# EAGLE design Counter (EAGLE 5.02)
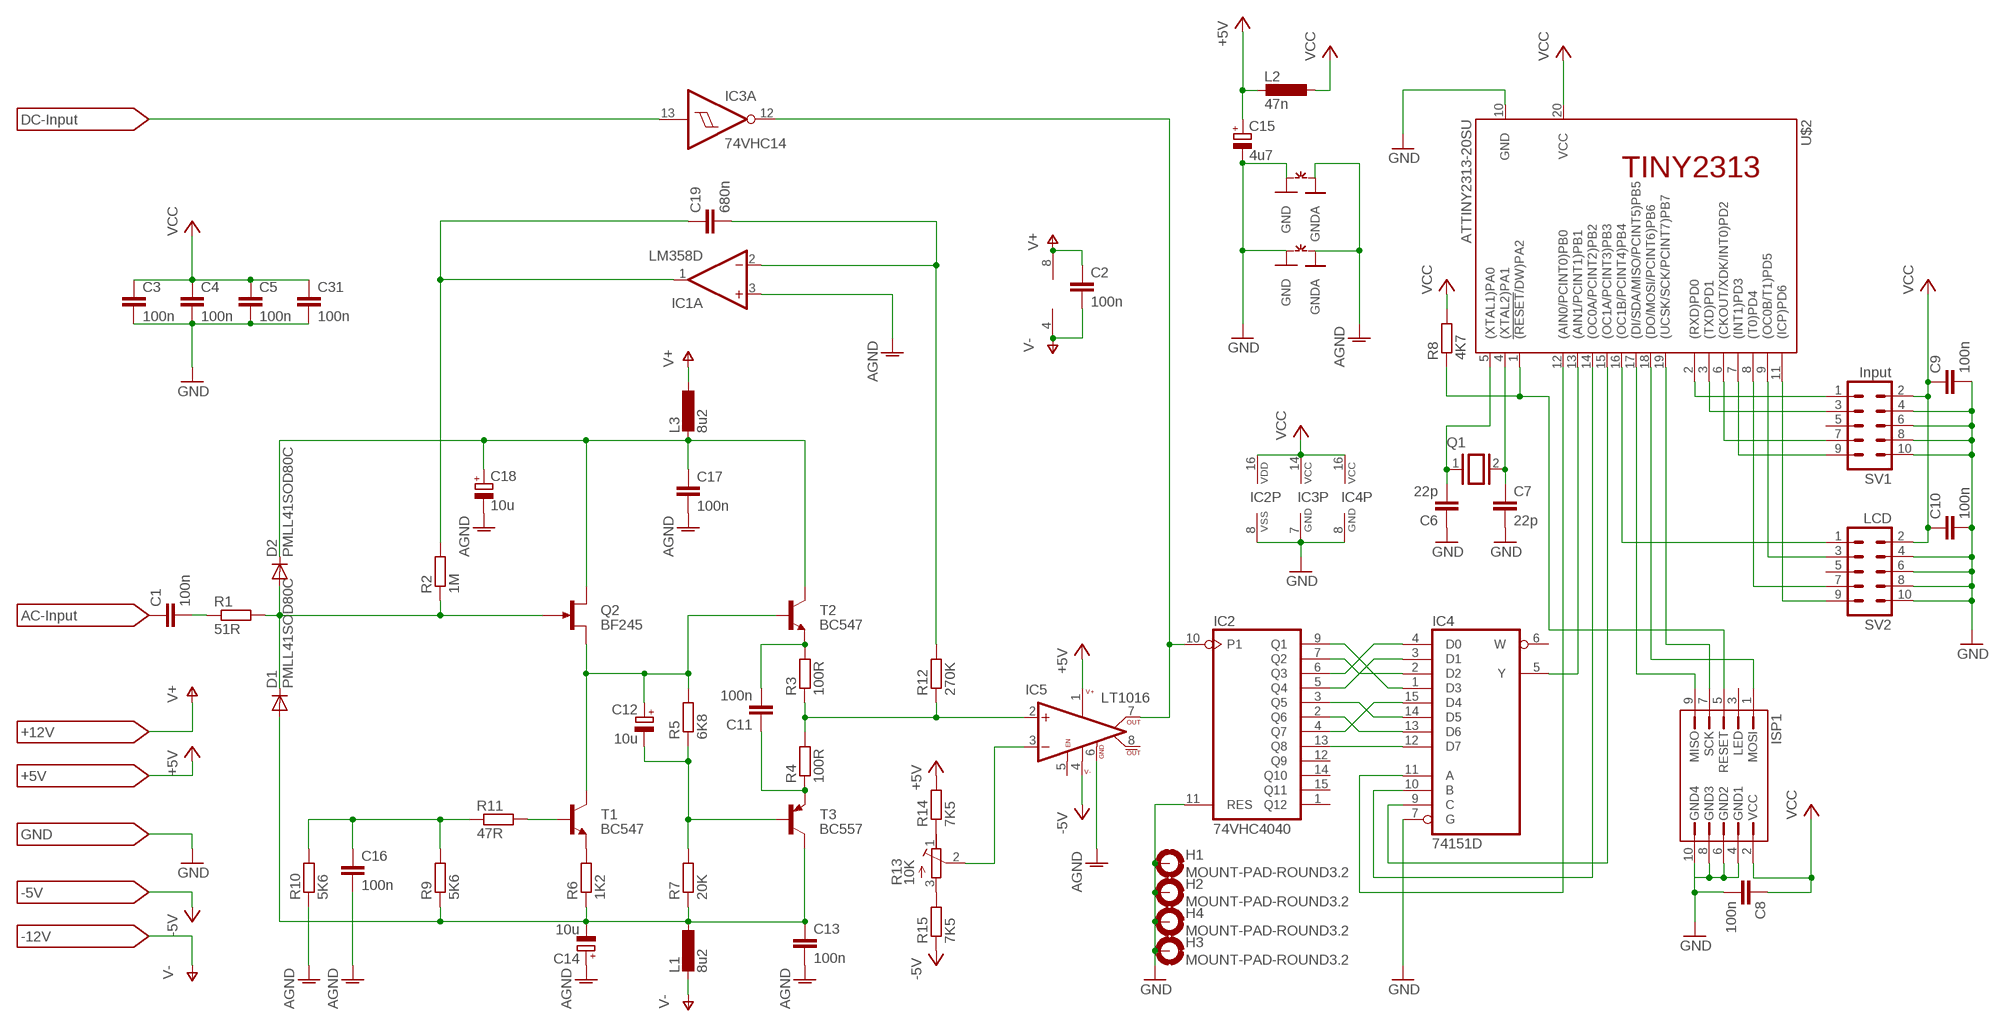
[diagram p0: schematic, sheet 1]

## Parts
C1  100n  C-EUC0603  [C0603]
C2  100n  C-EUC0603  [C0603]
C3  100n  C-EUC0603  [C0603]
C4  100n  C-EUC0603  [C0603]
C5  100n  C-EUC0603  [C0603]
C6  22p  C-EUC0603  [C0603]
C7  22p  C-EUC0603  [C0603]
C8  100n  C-EUC0603  [C0603]
C9  100n  C-EUC0603  [C0603]
C10  100n  C-EUC0603  [C0603]
C11  100n  C-EUC0603  [C0603]
C12  10u  CPOL-EUE2.5-5  [E2,5-5]
C13  100n  C-EUC0603  [C0603]
C14  10u  CPOL-EUE2.5-5  [E2,5-5]
C15  4u7  CPOL-EUE2.5-5  [E2,5-5]
C16  100n  C-EUC0603  [C0603]
C17  100n  C-EUC0603  [C0603]
C18  10u  CPOL-EUE2.5-5  [E2,5-5]
C19  680n  C-EUC0603  [C0603]
C31  100n  C-EUC0603  [C0603]
D1  PMLL41SOD80C  [SOD80C]
D2  PMLL41SOD80C  [SOD80C]
H1  MOUNT-PAD-ROUND3.2  [3,2-PAD]
H2  MOUNT-PAD-ROUND3.2  [3,2-PAD]
H3  MOUNT-PAD-ROUND3.2  [3,2-PAD]
H4  MOUNT-PAD-ROUND3.2  [3,2-PAD]
IC1  LM358D  [SO08]
IC2  74VHC4040  4040D  [SO16]
IC3  74VHC14  74HCT14D  [SO14]
IC4  74151D  [SO16]
IC5  LT1016  LT1016CS8  [SOIC8]
ISP1  AVR-ISP-10  [ML10]
L1  8u2  L-EU0207/10  [0207/10]
L2  47n  L-EU0207/10  [0207/10]
L3  8u2  L-EU0207/10  [0207/10]
Q1  XTAL/S  [QS]
Q2  BF245  [SOT54C]
R1  51R  R-EU_R0805  [R0805]
R2  1M  R-EU_R0805  [R0805]
R3  100R  R-EU_R0805  [R0805]
R4  100R  R-EU_R0805  [R0805]
R5  6K8  R-EU_R0805  [R0805]
R6  1K2  R-EU_R0805  [R0805]
R7  20K  R-EU_R0805  [R0805]
R8  4K7  R-EU_R0805  [R0805]
R9  5K6  R-EU_R0805  [R0805]
R10  5K6  R-EU_R0805  [R0805]
R11  47R  R-EU_R0805  [R0805]
R12  270K  R-EU_R0805  [R0805]
R13  10K  R-TRIMM43P  [RTRIM43P]
R14  7K5  R-EU_R0805  [R0805]
R15  7K5  R-EU_R0805  [R0805]
SV1  Input  ML10  [ML10]
SV2  LCD  ML10  [ML10]
T1  BC547  [TO92]
T2  BC547  [TO92]
T3  BC557  [TO92]
U$1  +12V  LABEL-R  [CON-1]
U$2  ATTINY2313-20SU  [SOIC20S]
U$3  AC-Input  LABEL-R  [CON-1]
U$4  +5V  LABEL-R  [CON-1]
U$5  GND  LABEL-R  [CON-1]
U$6  DC-Input  LABEL-R  [CON-1]
U$7  -5V  LABEL-R  [CON-1]
U$8  -12V  LABEL-R  [CON-1]
~NUDEV~1  GND-GNDA1,27MM  [GND-GNDA-1,27MM]
~NUDEV~2  GND-GNDA1,27MM  [GND-GNDA-1,27MM]

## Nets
+5V [power]: C15.+ IC5.1(V+) L2.2 R14.2 U$4.P$1
-5V: IC5.4(V-) R15.1 U$7.P$1
AGND: C13.2 C14.+ C16.2 C17.2 C18.- IC1.3(A:+IN) IC5.6(GND) R10.1 ~NUDEV~1.GNDA ~NUDEV~2.GNDA
CLOCK [special]: IC3.13(A:I) U$6.P$1
GND: C3.2 C4.2 C5.2 C6.1 C7.2 C8.2 C9.2 C10.2 C15.- C31.2 H1.B3,2(MOUNT) H2.B3,2(MOUNT) H3.B3,2(MOUNT) H4.B3,2(MOUNT) IC2.8(VSS) IC2.11(RES) IC3.7(P:GND) IC4.7(G) IC4.8(GND) ISP1.4(GND1) ISP1.6(GND2) ISP1.8(GND3) ISP1.10(GND4) SV1.4 SV1.6 SV1.8 SV1.10 SV2.4 SV2.6 SV2.8 SV2.10 U$2.10(GND) U$5.P$1 ~NUDEV~1.GND ~NUDEV~2.GND
N$1: C1.1 U$3.P$1
N$2: C1.2 R1.1
N$3: IC2.10(P1) IC3.12(A:O) IC5.7(OUT)
N$4: D1.C D2.A Q2.G R1.2 R2.1
N$5: IC4.5(Y) U$2.13((AIN1/PCINT1)PB1)
N$6: IC2.13(Q8) IC4.12(D7)
N$7: C16.1 R9.2 R10.2 R11.1
N$8: IC5.2(+IN) R3.1 R4.2 R12.1
N$9: IC4.11(A) U$2.12((AIN0/PCINT0)PB0)
N$10: IC2.2(Q6) IC4.13(D6)
N$11: IC2.3(Q5) IC4.14(D5)
N$12: IC2.4(Q7) IC4.15(D4)
N$13: IC2.5(Q4) IC4.3(D1)
N$14: IC2.6(Q3) IC4.4(D0)
N$15: IC2.7(Q2) IC4.2(D2)
N$16: IC2.9(Q1) IC4.1(D3)
N$17: C11.2 R3.2 T2.1(E)
N$18: C6.2 Q1.1 U$2.5((XTAL1)PA0)
N$19: C7.1 Q1.2 U$2.4((XTAL2)PA1)
N$20: ISP1.7(SCK) U$2.19((UCSK/SCK/PCINT7)PB7)
N$21: IC4.10(B) U$2.14((OC0A/PCINT2)PB2)
N$22: IC4.9(C) U$2.15((OC1A/PCINT3)PB3)
N$23: ISP1.1(MOSI) U$2.18((DO/MOSI/PCINT6)PB6)
N$24: ISP1.9(MISO) U$2.17((DI/SDA/MISO/PCINT5)PB5)
N$25: ISP1.5(RESET) R8.1 U$2.1(!(RESET!/DW)PA2)
N$26: C11.1 R4.1 T3.1(E)
N$27: R11.2 T1.2(B)
N$29: C12.+ Q2.S R5.2 T1.3(C) T2.2(B)
N$30: SV1.1 U$2.2((RXD)PD0)
N$31: SV1.3 U$2.3((TXD)PD1)
N$32: SV1.7 U$2.6((CKOUT/XDK/INT0)PD2)
N$33: SV1.9 U$2.7((INT1)PD3)
N$34: SV2.1 U$2.16((OC1B/PCINT4)PB4)
N$35: SV2.3 U$2.9((OC0B/T1)PD5)
N$36: SV2.7 U$2.8((T0)PD4)
N$37: SV2.9 U$2.11((ICP)PD6)
N$38: C12.- R5.1 R7.2 T3.2(B)
N$39: C17.1 C18.+ D2.C L3.2 Q2.D T2.3(C)
N$40: R6.2 T1.1(E)
N$41: C13.1 C14.- D1.A L1.1 R6.1 R7.1 R9.1 T3.3(C)
N$42: C19.2 IC1.2(A:-IN) R12.2
N$44: C19.1 IC1.1(A:OUT) R2.2
N$45: R13.1(A) R14.1
N$46: R13.3(E) R15.2
N$47: IC5.3(-IN) R13.2(S)
V+: C2.1 IC1.8(P:V+) L3.1 U$1.P$1
V-: C2.2 IC1.4(P:V-) L1.2 U$8.P$1
VCC: C3.1 C4.1 C5.1 C8.1 C9.1 C10.1 C31.1 IC2.16(VDD) IC3.14(P:VCC) IC4.16(VCC) ISP1.2(VCC) L2.1 R8.2 SV1.2 SV2.2 U$2.20(VCC)
Unconnected: IC1.5(B:+IN) IC1.6(B:-IN) IC1.7(B:OUT) IC2.1(Q12) IC2.12(Q9) IC2.14(Q10) IC2.15(Q11) IC3.1(D:I) IC3.2(D:O) IC3.3(E:I) IC3.4(E:O) IC3.5(F:I) IC3.6(F:O) IC3.8(C:O) IC3.9(C:I) IC3.10(B:O) IC3.11(B:I) IC4.6(W) IC5.5(LA_EN) IC5.8(!OUT) ISP1.3(LED) SV1.5 SV2.5

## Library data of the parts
C1-C11 C13 C16 C17 C19 C31 = rcl:C-EU: CAPACITOR, European symbol
C12 C14 C15 C18 = rcl:CPOL-EU: POLARIZED CAPACITOR, European symbol
D1 D2 = diode:PMLL41*: High-speed diodes
H1-H4 = holes:MOUNT-PAD-ROUND: MOUNTING PAD, round
IC1 = linear:LM358: OP AMP also LM158; LM258; LM2904 Source: http://cache.national.com/ds/LM/LM158.pdf
IC2 = 40xx:4040: 12-stage binary/ripple COUNTER
IC3 = 74xx-eu:74*14: Hex schmitt trigger INVERTER
IC4 = 74xx-eu:74*151: Data SELECTOR/MULTIPLEXER
IC5 = linear-technology:LT1016: Ultra-fast precision COMPARATOR
ISP1 = myStuff:AVR-ISP-10
L1-L3 = rcl:L-EU: INDUCTOR, European symbol
Q1 = special:XTAL/S: CRYSTAL
Q2 = transistor-small-signal:BF245: N-CHANNEL FET http://www.onsemi.com/pub/Collateral/BF245A-D.PDF
R1-R12 R14 R15 = rcl:R-EU_: RESISTOR, European symbol
R13 = rcl:R-TRIMM: Trimm resistor
SV1 SV2 = con-harting-ml:ML10: HARTING
T1 T2 = transistor:BC547: NPN TRANSISTOR
T3 = transistor-pnp:BC557: PNP Transistor
U$1 U$3-U$8 = myStuff:LABEL-R
U$2 = myStuff:ATTINY2313
~NUDEV~1 ~NUDEV~2 = ground-junctions:GND-GNDA: Connect GND - GNDA without DRC-Error, display layer 53 (54) to make copper (ROUTE) from GND to GNDA

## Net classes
1 special: clearance 0.508 mm
2 power: drill 0.762 mm, clearance 0.559 mm

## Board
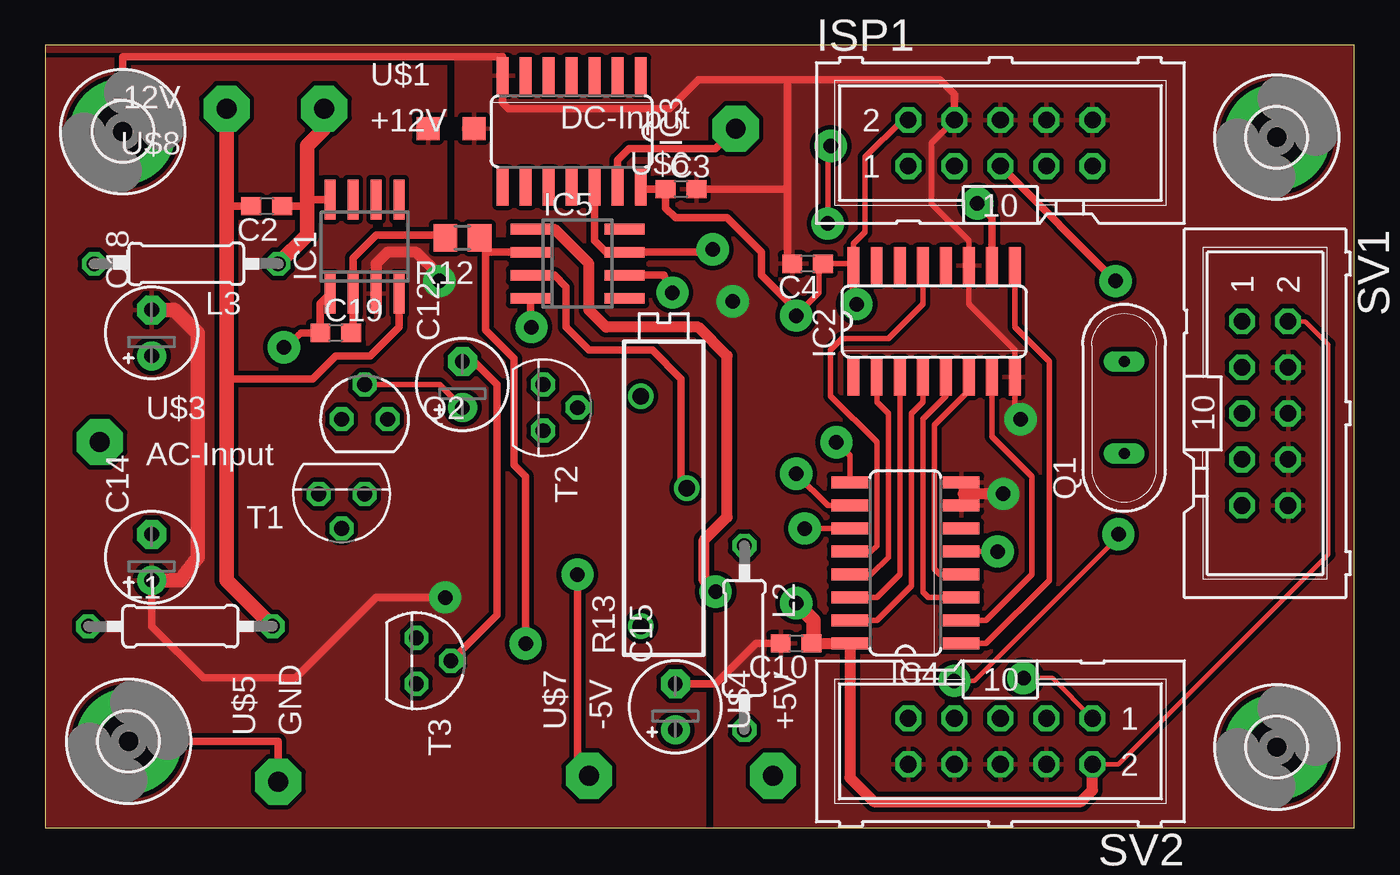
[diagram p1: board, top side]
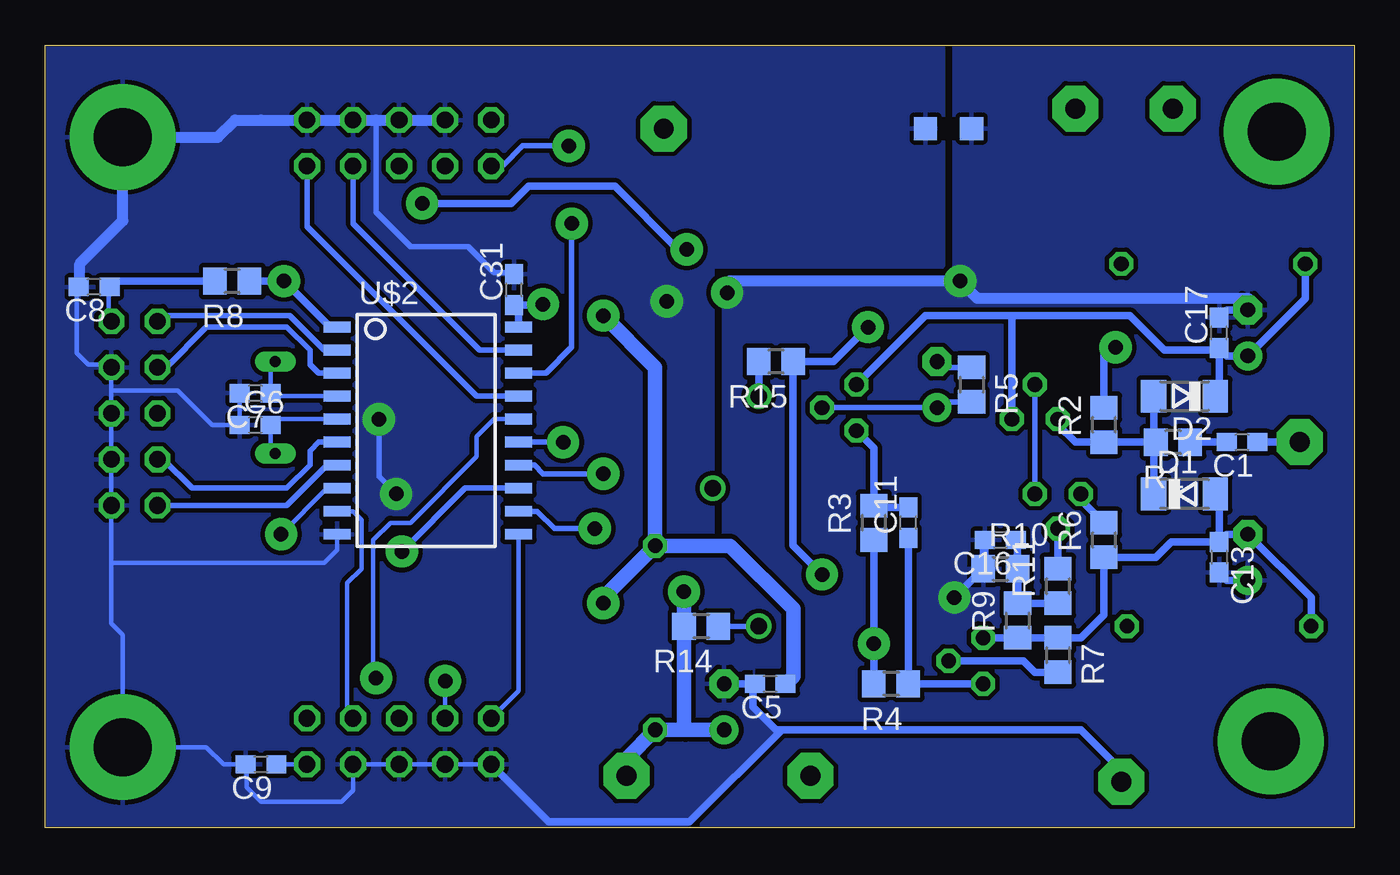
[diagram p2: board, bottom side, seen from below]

Size 72.22 x 43.17 mm. Coordinates in mm from the lower left corner, seen from the top.
Outline: 0,0 72.22,0 72.22,43.17 0,43.17 0,0
Copper layers (1*16): Top 0.035mm / dielectric 1.5mm / Bottom 0.035mm
Design rules "default *": minimum track width 10mil, minimum drill 24mil, track to track 10mil, track to pad 25mil, pad to pad 8mil, via to via 8mil, smd to smd 8mil, copper to edge 2mil, drill to drill 8mil, minimum pad ring 10mil, minimum via ring 8mil, stop-mask expansion 4mil, vias tented up to drill 0mil, thermal gap 10mil

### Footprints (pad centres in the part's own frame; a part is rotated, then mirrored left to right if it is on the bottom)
C0603 = smd 1.1 x 1: 1 -0.85,0; 2 0.85,0
E2,5-5 = drill 0.813 pad 1.6 round: + -1.27,0 | drill 0.813 pad 1.6 octagon: - 1.27,0
SOD80C = smd 1.4 x 1.8: A 1.7,0; C -1.7,0
3,2-PAD = drill 3.2 pad 5.842 round: B3,2 0,0
SO08 = smd 0.6 x 2.2: 1 -1.905,-2.6; 2 -0.635,-2.6; 3 0.635,-2.6; 4 1.905,-2.6; 5 1.905,2.6; 6 0.635,2.6; 7 -0.635,2.6; 8 -1.905,2.6
SO16 = smd 0.66 x 2.032: 1 -4.445,-3.073; 2 -3.175,-3.073; 3 -1.905,-3.073; 4 -0.635,-3.073; 5 0.635,-3.073; 6 1.905,-3.073; 7 3.175,-3.073; 8 4.445,-3.073; 9 4.445,3.073; 10 3.175,3.073; 11 1.905,3.073; 12 0.635,3.073; 13 -0.635,3.073; 14 -1.905,3.073; 15 -3.175,3.073; 16 -4.445,3.073
SO14 = smd 0.66 x 2.032: 1 -3.81,-3.073; 2 -2.54,-3.073; 3 -1.27,-3.073; 4 0,-3.073; 5 1.27,-3.073; 6 2.54,-3.073; 7 3.81,-3.073; 8 3.81,3.073; 9 2.54,3.073; 10 1.27,3.073; 11 0,3.073; 12 -1.27,3.073; 13 -2.54,3.073; 14 -3.81,3.073
SOIC8 = smd 0.6 x 2.2: 1 -1.905,-2.6; 2 -0.635,-2.6; 3 0.635,-2.6; 4 1.905,-2.6; 5 1.905,2.6; 6 0.635,2.6; 7 -0.635,2.6; 8 -1.905,2.6
ML10 = drill 0.914 octagon: 1 -5.08,-1.27; 2 -5.08,1.27; 3 -2.54,-1.27; 4 -2.54,1.27; 5 0,-1.27; 6 0,1.27; 7 2.54,-1.27; 8 2.54,1.27; 9 5.08,-1.27; 10 5.08,1.27
0207/10 = drill 0.813 octagon: 1 -5.08,0; 2 5.08,0
QS = drill 0.61 long: 1 -2.54,0; 2 2.54,0
SOT54C = drill 0.813 octagon: D 1.27,0; G -1.27,0; S 0,1.905
R0805 = smd 1.3 x 1.5: 1 -0.95,0; 2 0.95,0
RTRIM43P = drill 0.9 round: 1 -7.62,1.27; 2 0,-1.27; 3 5.08,1.27
TO92 = drill 0.813 octagon: 1 1.27,0; 2 0,1.905; 3 -1.27,0
CON-1 = drill 1.1 pad 2.54 octagon: P$1 0,0
SOIC20S = smd 0.6 x 1.5: 1 -5.715,-5; 2 -4.445,-5; 3 -3.175,-5; 4 -1.905,-5; 5 -0.635,-5; 6 0.635,-5; 7 1.905,-5; 8 3.175,-5; 9 4.445,-5; 10 5.715,-5; 11 5.715,5; 12 4.445,5; 13 3.175,5; 14 1.905,5; 15 0.635,5; 16 -0.635,5; 17 -1.905,5; 18 -3.175,5; 19 -4.445,5; 20 -5.715,5
GND-GNDA-1,27MM = smd 1.27 x 1.27: GND -1.27,0; GNDA 1.27,0

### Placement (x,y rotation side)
C1  6.18,21.27 180 bottom
C2  12.22,34.29 180 top
C3  35.08,35.24 0 top
C4  42.06,31.11 180 top
C5  32.22,7.93 180 bottom
C6  60.64,22.22 0 bottom
C7  60.64,23.97 180 bottom
C8  69.53,29.84 180 bottom
C9  60.32,3.49 180 bottom
C10  41.43,10.15 180 top
C11  24.6,16.82 90 bottom
C12  23.01,24.44 90 top
C13  7.46,14.92 270 bottom
C14  5.87,14.92 90 top
C15  34.76,6.66 90 top
C16  19.52,15.87 180 bottom
C17  7.46,27.3 90 bottom
C18  5.87,27.3 90 top
C19  16.03,27.3 0 top
C31  46.35,29.68 90 bottom
D1  9.36,18.41 0 bottom
D2  9.36,23.81 180 bottom
H1  4.28,38.41 0 top
H2  4.6,4.76 0 top
H3  67.94,38.09 0 top
H4  67.94,4.44 0 top
IC1  17.61,32.06 0 top
IC2  49.05,27.94 0 top
IC3  29.04,38.41 180 top
IC4  47.46,14.6 90 top
IC5  29.36,31.11 270 top
ISP1  52.7,37.78 0 top
L1  7.46,11.11 0 top
L2  38.57,10.47 270 top
L3  7.77,31.11 180 top
Q1  59.52,23.17 90 top
Q2  17.61,22.54 0 top
R1  10,21.27 180 bottom
R2  13.81,22.22 90 bottom
R3  26.5,16.82 90 bottom
R4  25.55,7.93 180 bottom
R5  21.11,24.44 270 bottom
R6  13.81,15.87 90 bottom
R7  16.34,9.52 270 bottom
R8  61.91,30.16 180 bottom
R9  18.57,11.42 90 bottom
R10  19.52,14.28 0 bottom
R11  16.34,13.33 90 bottom
R12  23.01,32.54 180 top
R13  34.12,18.73 90 top
R14  36.03,11.11 180 bottom
R15  31.9,25.71 180 bottom
SV1  67.3,22.85 270 top
SV2  52.7,4.76 180 top
T1  16.34,18.41 180 top
T2  27.46,23.17 270 top
T3  20.47,9.2 270 top
U$1  15.39,39.68 0 top
U$2  51.11,21.9 270 bottom
U$3  3.01,21.27 0 top
U$4  40.16,2.85 90 top
U$5  12.85,2.54 90 top
U$6  38.09,38.57 180 top
U$7  30,2.85 90 top
U$8  10,39.68 180 top
~NUDEV~1  22.38,38.57 180 top
~NUDEV~2  22.38,38.57 0 bottom

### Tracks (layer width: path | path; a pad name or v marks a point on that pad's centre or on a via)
+5V  (via drill 0.8 pad 1.78)
  Top 0.406: 28.09,33.01 IC5.1
  Top 0.61: 28.09,33.01 30,31.11 30,28.57 30.95,27.62 36.03,27.62 37.62,26.03 37.62,17.14 36.35,15.87 36.35,13.65 v36.98,13.01
  Bottom 0.813: U$4.P$1 40.16,3.8 L2.2 36.98,5.39 | 36.98,5.39 R14.2 v36.98,13.01 | C15.+ 36.98,5.39 36.83,5.39 36.98,5.39
-5V  (via drill 0.8 pad 1.78)
  Top 0.406: IC5.4 26.76,27.68 v26.82,27.62 | v29.36,13.97 29.36,3.49 U$7.P$1
  Bottom 0.406: v26.82,27.62 28.73,25.71 R15.1 30.95,15.56 v29.36,13.97
AGND  (via drill 0.8 pad 1.78)
  Top 0.406: v22.06,12.69 18.25,12.69 13.81,8.25 8.73,8.25 5.87,11.11 C14.+ | v34.6,29.52 34.12,30.47 IC5.6
  Top 0.61: IC1.3 18.25,31.11 18.88,31.75 20.47,31.75 21.74,30.47 v21.74,30.16
  Top 0.813: C18.- 7.14,28.57 8.41,27.3 8.41,14.92 7.46,13.65 C14.+
  Bottom 0.406: C14.+ 7.04,13.65 C13.2 | C18.- 7.04,28.57 C17.2 | R10.1 20.47,15.77 C16.2 20.37,14.38 v22.06,12.69 | 34.44,30.16 v34.6,29.52
  Bottom 0.61: C18.- 5.87,29.2 20.79,29.2 v21.74,30.16 34.44,30.16
  pour Top: -0.48,0 -0.48,42.38 22.06,42.38 22.06,31.9 29.05,31.9 29.84,31.11 29.84,28.57 30.95,27.46 36.03,27.46 37.46,26.03 37.46,17.78 36.35,16.66 36.35,-0.16
  pour Bottom: -0.01,43.18 22.06,43.18 22.06,30.16 34.76,30.16 34.76,16.19 30.79,12.22 30.79,8.41 31.43,7.77 33.17,7.77 33.33,7.62 33.33,6.82 31.9,5.39 31.11,5.07 36.82,-0.64 -0.01,-0.64
CLOCK
  Top 0.406: IC3.13 31.58,36.83 32.22,37.46 36.98,37.46 U$6.P$1
GND  (via drill 0.8 pad 1.78)
  Top 0.305: 50.53,18.31 IC4.8 | 50.53,18.31 IC4.7 | 50.63,18.41 50.53,18.31 | v53.81,22.54 53.49,22.85 IC2.8 53.49,26.35 50.95,28.89 IC2.11 50.95,32.38 48.89,34.44 48.89,37.78 ISP1.4
  Top 0.406: H1.B3,2 4.28,42.54 25.23,42.54 IC3.7 25.23,40 25.55,39.68 34.44,39.68 36.03,41.27 40.95,41.27 | H2.B3,2 12.85,4.76 U$5.P$1 | 40.95,41.27 40.95,35.4 | 40.95,35.4 | 40.95,35.24 40.95,31.27 41.11,31.11 41.11,31.21 C4.2 | 40.95,35.24 40.16,35.24 C3.2 | C15.- 36.98,7.93 39.2,10.15 C10.2 | 40.95,35.4 40.95,35.24 | 40.95,41.27 49.37,41.27 50.16,40.48 ISP1.4 | ISP1.4
  Top 0.61: v52.86,18.41 50.63,18.41
  Bottom 0.254: C7.2 C6.1 63.02,22.22 64.92,24.13 68.57,24.13 | 68.57,24.13 SV1.4 68.57,25.55 69.84,25.55 70.48,26.19 70.48,29.74 C8.2 70.32,29.9 | 68.57,24.13 SV1.6 SV1.8 SV1.10 68.57,16.19 | 68.57,16.19 68.57,14.6 56.83,14.6 56.11,15.32 U$2.10 | 68.57,16.19 | 68.57,16.19 68.57,11.27 67.94,10.63 H4.B3,2 63.34,4.44 62.38,3.49 C9.2 61.11,3.43 61.11,2.22 60.32,1.42 55.87,1.42 55.24,2.06 SV2.4 SV2.6 | SV2.10 | SV2.10 SV2.8 SV2.6 | SV2.6 52.86,3.49 | 52.86,3.49 | SV2.6 52.86,3.49 | SV2.6 | 60.32,39.05
  Bottom 0.305: v53.81,22.54 53.81,19.36 v52.86,18.41 | 46.29,30.63 47.46,30.63 48.89,32.06 52.06,32.06 53.97,33.97 53.97,39.05 | 53.97,39.05
  Bottom 0.406: C15.- C5.2 33.17,7.83 33.17,6.66 31.9,5.39 31.58,5.39 | 31.58,5.39 15.08,5.39 12.85,3.17 U$5.P$1 | 31.58,5.39 36.66,0.31 44.44,0.31 SV2.10
  Bottom 0.61: ISP1.6 ISP1.4 | ISP1.6 52.86,39.05 | 52.86,39.05 | ISP1.6 52.86,39.05 | ISP1.6 | ISP1.8 53.97,39.05 ISP1.6 | ISP1.8 | ISP1.8 | ISP1.10 ISP1.8 | 70.32,29.9 70.32,31.11 67.94,33.49 H3.B3,2 62.7,38.1 61.75,39.05 60.32,39.05 ISP1.10 | ISP1.10 | 46.29,30.63 C31.2
  other vias: 37.94,29.05
  pour Top: -0.48,44.29 -0.48,42.86 22.7,42.86 22.7,32.7 29.05,32.7 30.47,31.27 30.47,28.73 31.11,28.09 36.35,28.09 37.3,27.14 38.25,26.19 38.25,17.62 36.98,16.35 36.98,-0.32 72.86,-0.32 72.86,44.29
  pour Bottom: 22.7,43.65 22.7,30.95 35.39,30.95 35.39,14.76 34.76,14.76 31.74,11.74 31.74,8.88 33.17,8.88 33.17,6.66 31.74,5.23 37.62,-0.64 73.18,-0.64 73.18,43.65
N$1
  Bottom 0.406: C1.1 U$3.P$1
N$2
  Bottom 0.406: C1.2 R1.1
N$3  (via drill 0.8 pad 1.78)
  Top 0.406: IC3.12 30.31,32.38 30.95,31.75 IC5.7 36.82,31.75 v36.82,31.9 | v51.43,34.44 51.59,34.29 52.22,33.65 IC2.10
  Bottom 0.406: v36.82,31.9 37.3,31.9 40.79,35.4 45.55,35.4 46.51,34.44 v51.43,34.44
N$4
  Bottom 0.406: D1.C 11.06,21.15 R1.2 11.06,21.38 | 11.06,21.38 D2.A | 11.06,21.38 11.17,21.27 R2.1 15.4,21.27 16.34,22.22 Q2.G
N$5  (via drill 0.8 pad 1.78)
  Top 0.305: v52.54,15.24 IC4.5
  Bottom 0.305: U$2.13 49.05,18.73 v52.54,15.24
N$6
  Top 0.305: IC2.13 48.41,28.89 46.51,26.98 43.97,26.98 43.33,26.35 43.33,23.81 45.87,21.27 45.87,15.55 45.55,15.24 IC4.12
N$7
  Bottom 0.406: R11.1 R9.2 R10.2 18.57,15.77 C16.1
N$8  (via drill 0.8 pad 1.78)
  Top 0.406: R12.1 24.28,32.54 24.28,31.75 | 24.28,31.75 IC5.2 | 24.28,31.75 24.28,27.46 25.87,25.87 25.87,20 26.5,19.36 v26.5,10.15
  Bottom 0.406: R4.2 26.5,9.2 | R3.1 26.5,9.2 | v26.5,10.15 26.5,9.2
N$9  (via drill 0.8 pad 1.78)
  Top 0.305: v41.9,16.51 IC4.11
  Bottom 0.305: v41.9,16.51 44.13,16.51 45.08,17.46 U$2.12
N$10
  Top 0.305: IC2.2 45.87,23.49 46.51,22.85 46.51,14.92 45.55,13.97 IC4.13
N$11
  Top 0.305: IC2.3 47.14,13.97 45.87,12.69 IC4.14
N$12
  Top 0.305: IC2.4 48.41,23.49 47.78,22.85 47.78,13.33 45.87,11.42 IC4.15
N$13
  Top 0.305: IC2.5 49.68,23.81 48.41,22.54 48.41,13.01 48.73,12.69 IC4.3
N$14
  Top 0.305: IC2.6 50.95,24.12 49.05,22.22 49.05,14.28 49.37,13.97 IC4.4
N$15
  Top 0.305: IC2.7 52.22,21.58 54.45,19.36 54.45,13.97 51.91,11.42 IC4.2
N$16
  Top 0.305: IC2.9 53.49,27.62 55.4,25.71 55.4,13.65 51.91,10.15 IC4.1
N$17
  Bottom 0.406: C11.2 26.4,17.67 R3.2 26.5,20.95 T2.1
N$18
  Bottom 0.254: U$2.5 59.47,22.54 C6.2 59.79,20.89 Q1.1
N$19
  Bottom 0.254: U$2.4 59.63,23.81 C7.1 59.79,25.45 Q1.2 | Q1.2 | Q1.2
N$20
  Bottom 0.305: U$2.19 48.25,26.35 55.24,33.33 ISP1.7 | ISP1.7
N$21  (via drill 0.8 pad 1.78)
  Top 0.305: IC4.10 43.17,17.78 v41.43,19.52
  Bottom 0.305: v41.43,19.52 44.76,19.52 45.24,20 U$2.14
N$22  (via drill 0.8 pad 1.78)
  Top 0.305: IC4.9 44.39,20.53 v43.65,21.27
  Bottom 0.305: v43.65,21.27 U$2.15
N$23  (via drill 0.8 pad 1.78)
  Top 0.305: v43.17,33.33 43.17,35.4 43.17,37.62 v43.33,37.62
  Bottom 0.305: U$2.18 44.6,25.08 43.17,26.51 v43.17,33.33 | ISP1.1 | v43.33,37.62 45.87,37.62 46.98,36.51 ISP1.1
N$24
  Bottom 0.305: U$2.17 48.41,23.81 57.78,33.17 ISP1.9
N$25  (via drill 0.8 pad 1.78)
  Top 0.406: v59.05,30.16 | v59.05,30.16 52.86,36.35 ISP1.5 | ISP1.5
  Bottom 0.406: U$2.1 56.51,27.62 v59.05,30.16 | R8.1 v59.05,30.16 | v59.05,30.16 | v59.05,30.16
N$26
  Bottom 0.406: T3.1 R4.1 C11.1
N$27
  Bottom 0.406: R11.2 T1.2
N$29
  Top 0.305: Q2.S 21.74,24.44 C12.+
  Bottom 0.305: T1.3 Q2.S | R5.2 22.69,23.49 C12.+ T2.2
N$30
  Bottom 0.305: U$2.2 56.83,26.35 58.73,28.25 65.72,28.25 SV1.1
N$31
  Bottom 0.305: U$2.3 57.14,25.08 57.62,25.55 57.62,26.35 58.89,27.62 63.34,27.62 65.56,25.4 SV1.3 | SV1.3
N$32
  Bottom 0.305: U$2.6 57.14,21.27 57.62,20.79 57.62,20 58.89,18.73 64.13,18.73 65.72,20.32 SV1.7
N$33
  Bottom 0.305: U$2.7 56.67,20 58.89,17.78 SV1.9 | SV1.9
N$34  (via drill 0.8 pad 1.78)
  Top 0.254: v53.97,8.25 55.56,8.25 SV2.1
  Bottom 0.254: U$2.16 47.46,22.54 48.41,21.59 48.41,20.47 52.06,16.82 53.17,16.82 54.13,15.87 54.13,8.41 v53.97,8.25 | v53.97,8.25 | v53.97,8.25 53.97,8.41 v53.97,8.25
N$35
  Bottom 0.254: U$2.9 55.24,17.46 54.76,16.98 54.76,14.28 55.56,13.49 55.56,6.35 SV2.3 | SV2.3
N$36  (via drill 0.8 pad 1.78)
  Top 0.254: v59.21,16.19 59.21,16.03 51.27,8.09 v50.16,8.09
  Bottom 0.254: U$2.8 56.67,18.73 v59.21,16.19 | v50.16,8.09 50.16,6.19 SV2.7 | SV2.7
N$37
  Bottom 0.254: U$2.11 46.11,7.54 SV2.9 | SV2.9
N$38
  Top 0.406: T3.2 24.92,11.74 24.92,24.44 23.65,25.71 23.33,25.71 C12.-
  Bottom 0.305: R5.1 22.69,25.39 C12.-
  Bottom 0.406: T3.2 18.25,9.2 17.61,8.57 16.98,8.57 R7.2
N$39
  Bottom 0.406: L3.2 2.69,29.2 C18.+ 7.04,26.03 C17.1 7.46,26.35 | 7.46,26.35 7.46,24.01 D2.C | 18.88,28.25 Q2.D | 18.88,28.25 12.38,28.25 10.47,26.35 7.46,26.35 | T2.3 23.65,28.25 18.88,28.25
N$40
  Bottom 0.406: T1.1 15.08,18.09 R6.2
N$41
  Bottom 0.406: L1.1 2.38,12.69 C14.- 7.04,16.19 C13.1 | C13.1 7.46,18.21 D1.A | C13.1 10.1,15.77 10.95,14.92 R6.1 13.81,11.74 15.08,10.47 R7.1 17.61,10.47 R9.1 | T3.3 18.72,10.47 R9.1 | R9.1 18.88,10.47 19.04,10.63 18.09,10.63 17.93,10.47 R9.1
N$42
  Top 0.406: C19.2 16.98,27.4 IC1.2 16.98,31.43 18.25,32.7 21.74,32.7 R12.2
N$44  (via drill 0.8 pad 1.78)
  Top 0.406: v13.17,26.51 14.12,27.3 C19.1 15.18,28.93 IC1.1
  Bottom 0.406: R2.2 13.81,26.67 v13.17,26.51
N$45
  Bottom 0.305: R13.1 R14.1
N$46
  Bottom 0.406: R13.3 32.85,25.4 | 32.85,25.4 R15.2 | R15.2 32.85,25.4
N$47
  Top 0.406: IC5.3 28.09,30.47 28.73,29.84 28.73,27.62 30,26.35 33.49,26.35 35.08,24.76 35.08,19.04 R13.2
V+
  Top 0.406: 14.44,34.29 C2.1 | IC1.8 14.5,34.66 14.44,34.6
  Top 0.813: U$1.P$1 15.39,38.57 14.44,37.62 14.44,34.6 14.44,34.29 14.44,32.7 L3.1
V-
  Top 0.406: 10,34.29 C2.2 | IC1.4 19.52,27.62 17.93,26.03 16.03,26.03 14.76,24.76 10,24.76
  Top 0.813: U$8.P$1 10,34.29 10,24.76 10,13.65 L1.2
VCC  (via drill 0.8 pad 1.78)
  Top 0.254: SV1.2 69.53,27.94 70.8,26.67 70.8,15.08 59.21,3.49 SV2.2 | SV2.2
  Top 0.305: IC2.16 44.5,31.01 44.6,31.11 | v41.43,28.25 42.7,29.52 42.7,31.11 | 42.7,31.11 44.6,31.11 | 42.7,31.11 42.86,31.17 C4.1 | 44.6,31.11 44.6,32.22 45.24,32.86 45.24,36.98 47.3,39.05 ISP1.2
  Top 0.406: IC3.14 32.96,35.24 C3.1 34.23,34.18 34.76,33.65 37.62,33.65 39.52,31.75 39.52,30.47 41.11,28.89 v41.43,28.25 | v44.76,28.89 | v44.76,28.89 44.6,29.05 44.6,31.11
  Top 0.61: 42.38,10.15 IC4.16 44.39,2.75 45.71,1.42 57.14,1.42 57.78,2.06 SV2.2 | SV2.2
  Top 0.813: v41.43,12.38 42.38,11.42 42.38,10.15 42.22,10.1 C10.1
  Bottom 0.254: SV2.2 C9.1 | SV1.2 68.73,28.25 68.73,29.84 C8.1
  Bottom 0.406: R8.2 68.2,30.16 C8.1 | U$2.20 46.11,28.75 C31.1 44.86,28.83 v44.76,28.89
  Bottom 0.813: L2.1 41.43,12.69 v41.43,12.38 | L2.1 38.57,25.4 v41.43,28.25 | L2.1 34.44,15.55 30.95,12.06 30.95,8.35 C5.1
